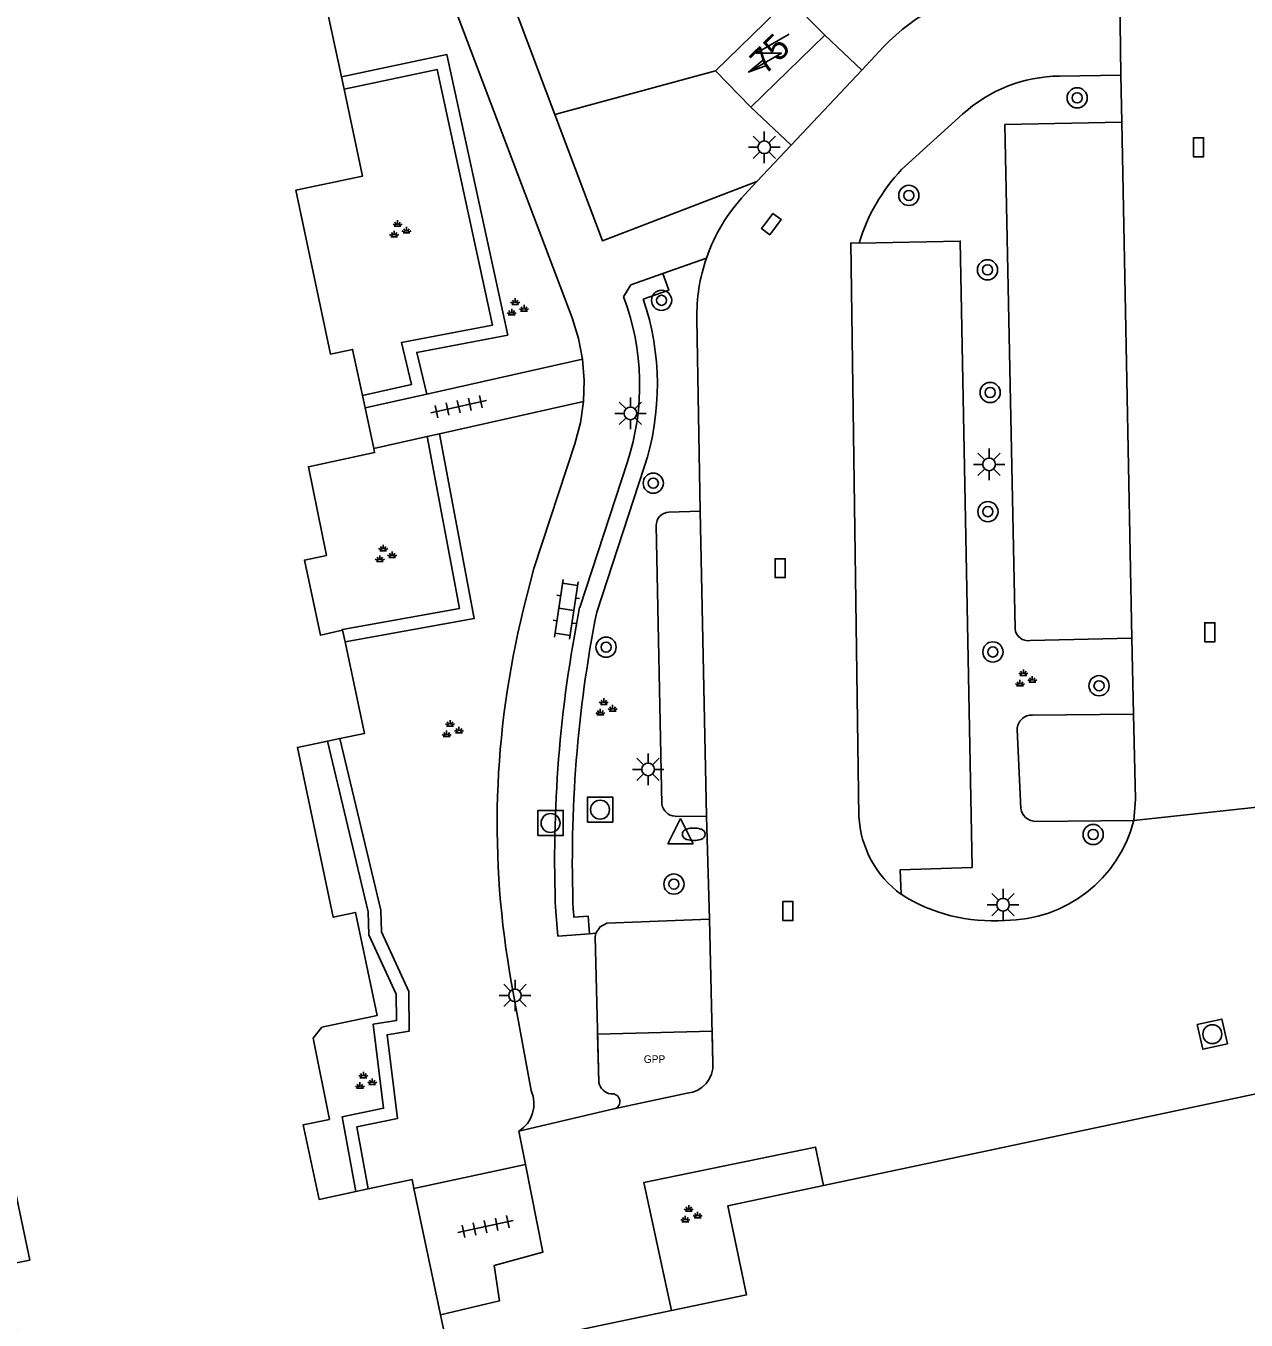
# Model space of a CAD drawing. Extents: x 132998 to 136004, y 396998 to 398512.
# Drawn here: x 133155.2 to 133203.5, y 397650.9 to 397702.1 of the extents above; entities that cross this region are included whole.
import ezdxf

# ---------------------------------------------------------------- set-up
doc = ezdxf.new("R2010")
doc.units = 0
for name, color, linetype in [('bp-grn-parkeervak', 7, 'Continuous'), ('gg-anno-huisnummerreeks BGT', 7, 'Continuous'), ('gg-bbg-hoofdgebouw', 7, 'Continuous'), ('gg-knt-verharding', 7, 'Continuous'), ('gg-knt-verharding nz', 7, 'Continuous'), ('gt-grn-groengrens', 7, 'Continuous'), ('gt-grn-weggrens', 7, 'Continuous'), ('gt-symb-boom', 7, 'Continuous'), ('gt-symb-brandkraan', 7, 'Continuous'), ('gt-symb-groenvak', 7, 'Continuous'), ('gt-symb-klinker verharding', 7, 'Continuous'), ('gt-symb-kolk', 7, 'Continuous'), ('gt-symb-lichtmast', 7, 'Continuous'), ('gt-symb-rioolschacht', 7, 'Continuous'), ('gt-symb-tegel verharding', 7, 'Continuous'), ('gt-symb-trafo symbool', 7, 'Continuous'), ('gt-symb-waterafsluiter', 7, 'Continuous'), ('kenmerkpunt gehandicapten parkeerplaats', 7, 'Continuous')]:
    doc.layers.add(name, color=color, linetype=linetype)

# ---------------------------------------------------------------- blocks, each defined once
blk = doc.blocks.new('gt0-HSP')
at = {"layer": 'gt-symb-trafo symbool'}
for points in [[(0.771, 0.746), (-0.529, -0.004), (0.471, -0.004), (-0.829, -0.754)], [(-0.217, -0.24), (-0.829, -0.754), (-0.077, -0.48)]]:
    blk.add_lwpolyline(points, dxfattribs=at)
blk = doc.blocks.new('gt0-KOLK')
at = {"layer": 'gt-symb-kolk'}
blk.add_lwpolyline([(0, 0), (0.375, 0), (0.375, 0.4), (-0.375, 0.4), (-0.375, 0), (0, 0)], dxfattribs=at)
blk = doc.blocks.new('gt0-BOOM')
at = {"layer": 'gt-symb-boom'}
for radius in [0.4, 0.2]:
    blk.add_circle((0, 0), radius, dxfattribs=at)
blk = doc.blocks.new('gt0-LMAST')
at = {"layer": 'gt-symb-lichtmast'}
for p, q in [((-0.005, 0.246), (-0.005, 0.621)), ((-0.182, 0.173), (-0.447, 0.438)), ((0.172, 0.173), (0.437, 0.438)), ((-0.255, -0.004), (-0.63, -0.004)), ((-0.182, -0.181), (-0.447, -0.446)), ((-0.005, -0.254), (-0.005, -0.629)), ((0.437, -0.446), (0.172, -0.181)), ((0.245, -0.004), (0.62, -0.004))]:
    blk.add_line(p, q, dxfattribs=at)
blk.add_circle((-0.005, -0.004), 0.25, dxfattribs=at)
blk = doc.blocks.new('gt0-GRVAK')
at = {"layer": 'gt-symb-groenvak'}
for p, q in [((-0.11, 0.189), (-0.228, 0.24)), ((-0.182, 0.153), (0.088, 0.153)), ((-0.091, 0.211), (-0.156, 0.322)), ((-0.047, 0.214), (-0.047, 0.393)), ((-0.004, 0.211), (0.061, 0.322)), ((0.015, 0.189), (0.133, 0.24)), ((0.262, -0.052), (0.197, 0.059)), ((0.305, -0.049), (0.305, 0.13)), ((0.349, -0.052), (0.414, 0.059)), ((-0.245, -0.228), (-0.363, -0.177)), ((-0.318, -0.264), (-0.047, -0.264)), ((-0.226, -0.206), (-0.291, -0.095)), ((-0.183, -0.203), (-0.183, -0.024)), ((-0.139, -0.206), (-0.074, -0.095)), ((-0.12, -0.228), (-0.002, -0.177)), ((0.243, -0.074), (0.125, -0.023)), ((0.17, -0.11), (0.441, -0.11)), ((0.368, -0.074), (0.486, -0.023))]:
    blk.add_line(p, q, dxfattribs=at)
blk = doc.blocks.new('gt0-TEG1')
at = {"layer": 'gt-symb-tegel verharding'}
for p, q in [((-1.125, 0), (1.125, 0)), ((-0.9, -0.25), (-0.9, 0.25)), ((-0.45, -0.25), (-0.45, 0.25)), ((0, -0.25), (0, 0.25)), ((0.45, -0.25), (0.45, 0.25)), ((0.9, -0.25), (0.9, 0.25))]:
    blk.add_line(p, q, dxfattribs=at)
blk = doc.blocks.new('gt0-KL1')
at = {"layer": 'gt-symb-klinker verharding'}
for p, q in [((-1.15, 0.3), (1.15, 0.3)), ((-1, -0.3), (-1, 0.3)), ((-0.5, 0.3), (-0.5, 0.45)), ((0, -0.3), (0, 0.3)), ((0.5, 0.3), (0.5, 0.45)), ((1, -0.3), (1, 0.3)), ((-1.15, -0.3), (1.15, -0.3)), ((-0.5, -0.45), (-0.5, -0.3)), ((0.5, -0.45), (0.5, -0.3))]:
    blk.add_line(p, q, dxfattribs=at)
blk = doc.blocks.new('gt0-WAFSL')
at = {"layer": 'gt-symb-waterafsluiter'}
for p, q in [((-0.5, -0.333), (0, 0.667)), ((0, 0.667), (0.5, -0.333)), ((0.5, -0.333), (-0.5, -0.333))]:
    blk.add_line(p, q, dxfattribs=at)
blk = doc.blocks.new('gt0-BR')
at = {"layer": 'gt-symb-brandkraan'}
for centre, radius, start, end in [((-0.244, 0), 0.206, 107.5669, 252.4331), ((0.599, -2.664), 3, 106.892, 107.5669), ((0, -0.691), 0.938, 73.108, 106.892), ((-0.599, -2.664), 3, 72.4331, 73.108), ((0.244, 0), 0.206, 287.567, 72.4331), ((0.599, 2.664), 3, 252.4331, 253.108), ((0, 0.691), 0.938, 253.108, 286.8921), ((-0.599, 2.664), 3, 286.8921, 287.567)]:
    blk.add_arc(centre, radius, start, end, dxfattribs=at)
blk = doc.blocks.new('gt0-RS')
at = {"layer": 'gt-symb-rioolschacht'}
blk.add_lwpolyline([(-0.5, -0.5), (0.5, -0.5), (0.5, 0.5), (-0.5, 0.5)], close=True, dxfattribs=at)
blk.add_circle((0, 0), 0.375, dxfattribs=at)

msp = doc.modelspace()

# ---------------------------------------------------------------- linework, layer by layer
at = {"layer": 'bp-grn-parkeervak'}
msp.add_line((133181.369, 397659.853), (133178.468, 397659.234), dxfattribs=at)
msp.add_lwpolyline([(133177.868, 397660.275), (133177.821, 397662.195), (133182.356, 397662.305), (133182.387, 397661.036)], dxfattribs=at)
for centre, radius, start, end in [((133181.258, 397660.978), 1.131, 275.6543, 2.9202), ((133178.44, 397660.408), 0.587, 193.0963, 260.5107), ((133178.399, 397659.53), 0.304, 283.1378, 100.591)]:
    msp.add_arc(centre, radius, start, end, dxfattribs=at)
at = {"layer": 'gg-bbg-hoofdgebouw'}
for p, q in [((133185.41, 397703.17), (133182.49, 397700.32)), ((133186.82, 397701.73), (133185.41, 397703.17)), ((133183.89, 397698.88), (133186.82, 397701.73)), ((133167.778, 397699.597), (133167.674, 397700.086)), ((133182.49, 397700.32), (133183.89, 397698.88)), ((133168.613, 397686.983), (133168.509, 397687.472)), ((133168.613, 397686.983), (133168.954, 397685.378)), ((133167.72, 397678.18), (133167.817, 397677.727)), ((133167.617, 397673.895), (133167.128, 397673.792)), ((133168.245, 397655.962), (133168.734, 397656.067)), ((133170.545, 397656.088), (133171.605, 397651.087))]:
    msp.add_line(p, q, dxfattribs=at)
for points in [[(133166.109, 397703.604), (133166.89, 397703.77), (133167.674, 397700.086)], [(133168.509, 397687.472), (133168.12, 397689.3), (133167.24, 397689.11), (133165.87, 397695.6), (133168.51, 397696.16), (133167.778, 397699.597)], [(133168.954, 397685.378), (133168.99, 397685.21), (133166.37, 397684.65), (133167.08, 397681.14), (133166.21, 397680.96), (133166.84, 397677.99), (133167.72, 397678.18)], [(133167.817, 397677.727), (133168.59, 397674.1), (133167.617, 397673.895)], [(133167.128, 397673.792), (133165.93, 397673.54), (133167.35, 397666.82), (133168.23, 397667.01), (133169.09, 397662.93), (133166.9, 397662.47), (133166.56, 397662.04), (133167.2, 397658.82), (133166.16, 397658.6), (133166.8, 397655.65), (133168.245, 397655.962)], [(133208.423, 397668.156), (133207.16, 397667.88), (133208.621, 397660.83), (133186.764, 397656.201)], [(133149.37, 397663.02), (133150.13, 397659.49), (133149.26, 397659.31), (133150.14, 397655.25), (133154.72, 397656.2), (133155.33, 397653.25), (133154.28, 397653.04), (133155.02, 397649.49), (133154.14, 397649.3), (133155.02, 397645.23), (133159.57, 397646.22), (133160.98, 397639.7), (133157.32, 397638.9), (133158.87, 397631.35), (133159.76, 397631.53), (133160.49, 397627.99)], [(133168.734, 397656.067), (133170.47, 397656.44), (133170.545, 397656.088)], [(133186.764, 397656.201), (133182.98, 397655.4), (133183.71, 397651.87), (133180.745, 397651.249)], [(133171.605, 397651.087), (133171.96, 397649.41), (133180.745, 397651.249)]]:
    msp.add_lwpolyline(points, dxfattribs=at)
at = {"layer": 'gg-knt-verharding'}
for p, q in [((133170.9, 397712.5), (133176.132, 397698.591)), ((133186.82, 397701.73), (133188.283, 397700.355)), ((133188.283, 397700.355), (133189.146, 397701.273)), ((133185.487, 397697.379), (133188.283, 397700.355)), ((133198.54, 397700.15), (133196.108, 397700.117)), ((133198.579, 397698.294), (133198.54, 397700.15)), ((133183.89, 397698.88), (133185.487, 397697.379)), ((133192.276, 397698.609), (133189.86, 397696.42)), ((133193.953, 397698.204), (133198.579, 397698.294)), ((133193.953, 397698.204), (133194.356, 397678.239)), ((133184.132, 397695.938), (133185.487, 397697.379)), ((133183.642, 397695.417), (133184.132, 397695.938)), ((133182.131, 397692.915), (133180.403, 397692.3)), ((133181.875, 397682.895), (133181.751, 397690.49)), ((133171.052, 397687.528), (133177.222, 397688.905)), ((133168.613, 397686.983), (133171.052, 397687.528)), ((133171.558, 397685.96), (133177.259, 397687.234)), ((133168.954, 397685.378), (133171.07, 397685.851)), ((133171.07, 397685.851), (133171.558, 397685.96)), ((133179.001, 397684.851), (133177.11, 397679.08)), ((133180.644, 397682.852), (133181.875, 397682.895)), ((133180.368, 397671.292), (133180.144, 397682.325)), ((133194.944, 397677.773), (133198.975, 397677.861)), ((133199.048, 397674.857), (133198.975, 397677.861)), ((133195.042, 397674.825), (133199.048, 397674.857)), ((133194.58, 397671.123), (133194.436, 397674.25)), ((133182.137, 397670.82), (133180.888, 397670.815)), ((133182.247, 397666.74), (133182.137, 397670.82)), ((133199.053, 397670.649), (133195.13, 397670.616)), ((133176.16, 397667.042), (133176.245, 397666.071)), ((133176.245, 397666.071), (133177.499, 397666.166)), ((133177.499, 397666.166), (133177.756, 397666.185)), ((133174.415, 397664.197), (133175.19, 397659.96)), ((133174.7, 397658.35), (133178.468, 397659.234)), ((133174.96, 397657.04), (133174.7, 397658.35)), ((133174.96, 397657.04), (133170.545, 397656.088))]:
    msp.add_line(p, q, dxfattribs=at)
for points in [[(133170.941, 397706.05), (133176.809, 397690.542), (133177.063, 397689.735), (133177.222, 397688.905)], [(133176.132, 397698.591), (133178.01, 397693.6), (133184.132, 397695.938)], [(133188.175, 397693.504), (133192.179, 397693.588), (133192.652, 397668.785), (133189.808, 397668.699), (133189.835, 397667.729)], [(133180.403, 397692.3), (133179.14, 397691.85), (133178.85, 397691.38)], [(133177.259, 397687.234), (133177.29, 397688.071), (133177.222, 397688.905)], [(133177.259, 397687.234), (133177.137, 397686.39), (133176.916, 397685.565), (133175.29, 397680.63), (133174.878, 397678.972)], [(133182.247, 397666.74), (133178.18, 397666.592), (133177.917, 397666.442), (133177.756, 397666.185)], [(133177.868, 397660.275), (133177.728, 397666.039), (133177.756, 397666.185)], [(133180.745, 397651.249), (133179.65, 397656.32), (133186.45, 397657.72), (133186.764, 397656.201)], [(133171.605, 397651.087), (133173.94, 397651.64), (133173.72, 397653.03), (133175.65, 397653.56), (133174.96, 397657.04)]]:
    msp.add_lwpolyline(points, dxfattribs=at)
for centre, radius, start, end in [((133194.576, 397696.168), 7.453, 95.9204, 136.7663), ((133196.186, 397694.295), 5.822, 90.7714, 132.1907), ((133195.175, 397691.404), 7.308, 136.6564, 163.301), ((133188.726, 397690.639), 6.977, 136.7804, 160.9627), ((133188.76, 397690.634), 7.011, 161.0117, 181.1766), ((133169.681, 397687.902), 9.806, 341.8745, 20.7753), ((133180.654, 397682.341), 0.511, 91.164, 181.848), ((133208.904, 397670.511), 35.062, 166.0358, 190.3744), ((133227.198, 397669.071), 51.079, 168.6993, 182.2762), ((133194.865, 397678.277), 0.51, 184.2585, 278.9466), ((133195.018, 397674.243), 0.582, 87.6818, 179.311), ((133180.916, 397671.368), 0.553, 187.8658, 267.0734), ((133195.167, 397671.208), 0.593, 188.2635, 266.3957), ((133193.955, 397671.963), 5.265, 269.9481, 345.5496), ((133193.441, 397673.394), 6.715, 237.521, 274.3475), ((133174.011, 397659.439), 1.289, 302.3196, 23.8254), ((133178.44, 397660.408), 0.587, 193.0963, 260.5107), ((133178.399, 397659.53), 0.304, 283.1378, 100.591)]:
    msp.add_arc(centre, radius, start, end, dxfattribs=at)
at = {"layer": 'gg-knt-verharding nz'}
for p, q in [((133198.579, 397698.294), (133198.975, 397677.861)), ((133182.137, 397670.82), (133181.875, 397682.895)), ((133182.387, 397661.036), (133182.247, 397666.74)), ((133178.468, 397659.234), (133181.369, 397659.853))]:
    msp.add_line(p, q, dxfattribs=at)
for points in [[(133188.17, 397670.811), (133187.849, 397693.516), (133188.175, 397693.504)], [(133199.048, 397674.857), (133199.116, 397671.495), (133199.053, 397670.649)]]:
    msp.add_lwpolyline(points, dxfattribs=at)
for centre, radius, start, end in [((133192.236, 397671.017), 4.072, 182.9011, 233.8577), ((133181.258, 397660.978), 1.131, 275.6543, 2.9202)]:
    msp.add_arc(centre, radius, start, end, dxfattribs=at)
at = {"layer": 'gt-grn-groengrens'}
for p, q in [((133176.132, 397698.591), (133182.49, 397700.32)), ((133179.666, 397684.633), (133177.788, 397678.902))]:
    msp.add_line(p, q, dxfattribs=at)
for points in [[(133171.052, 397687.528), (133170.657, 397689.177), (133174.259, 397689.865), (133171.843, 397700.973), (133167.674, 397700.086)], [(133167.778, 397699.597), (133171.46, 397700.38), (133173.661, 397690.26), (133170.049, 397689.57), (133170.447, 397687.905), (133168.509, 397687.472)], [(133180.403, 397692.3), (133180.638, 397691.64), (133179.629, 397691.281)], [(133167.72, 397678.18), (133167.712, 397678.216), (133172.347, 397679.046), (133171.07, 397685.851)], [(133171.558, 397685.96), (133172.931, 397678.643), (133167.817, 397677.727)], [(133167.128, 397673.792), (133168.732, 397667.032), (133168.762, 397666.12), (133169.84, 397663.772), (133169.85, 397662.732), (133168.929, 397662.588), (133169.346, 397659.258), (133167.708, 397658.922), (133168.245, 397655.962)], [(133167.617, 397673.895), (133169.23, 397667.099), (133169.258, 397666.237), (133170.339, 397663.884), (133170.354, 397662.305), (133169.485, 397662.169), (133169.9, 397658.861), (133168.287, 397658.53), (133168.734, 397656.067)], [(133177.499, 397666.166), (133177.446, 397666.864), (133176.882, 397666.821), (133176.859, 397667.086)]]:
    msp.add_lwpolyline(points, dxfattribs=at)
for centre, radius, start, end in [((133169.677, 397687.902), 10.51, 341.8806, 18.7572), ((133227.209, 397669.072), 50.39, 168.7504, 182.2586)]:
    msp.add_arc(centre, radius, start, end, dxfattribs=at)
at = {"layer": 'gt-grn-weggrens'}
for p, q in [((133198.5, 397703.74), (133198.54, 397700.15)), ((133199.053, 397670.649), (133207.636, 397671.584))]:
    msp.add_line(p, q, dxfattribs=at)

# ---------------------------------------------------------------- block references
at = {"layer": 'gt-symb-boom'}
for p in [(133196.812, 397699.254), (133190.147, 397695.392), (133193.261, 397692.445), (133180.354, 397691.24), (133193.364, 397687.591), (133180.025, 397684.003), (133193.276, 397682.875), (133178.155, 397677.509), (133193.474, 397677.321), (133197.677, 397675.985), (133197.443, 397670.094), (133180.842, 397668.134)]:
    msp.add_blockref('gt0-BOOM', p, dxfattribs=at)
at = {"layer": 'gt-symb-brandkraan'}
msp.add_blockref('gt0-BR', (133181.627, 397670.106), dxfattribs=at)
at = {"layer": 'gt-symb-groenvak'}
for p in [(133169.946, 397694.017), (133174.601, 397690.927), (133169.377, 397681.17), (133194.727, 397676.239), (133178.111, 397675.093), (133172.023, 397674.233), (133168.59, 397660.313), (133181.477, 397655.032)]:
    msp.add_blockref('gt0-GRVAK', p, dxfattribs=at)
at = {"layer": 'gt-symb-klinker verharding', "rotation": 81.43241009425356}
msp.add_blockref('gt0-KL1', (133176.582, 397679.006), dxfattribs=at)
at = {"layer": 'gt-symb-kolk'}
for p, rotation in [((133201.815, 397697.301), 90), ((133184.538, 397694.378), -126.5834211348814), ((133185.249, 397680.639), 90), ((133202.265, 397678.103), 90), ((133185.557, 397667.063), 90)]:
    msp.add_blockref('gt0-KOLK', p, dxfattribs=dict(at, rotation=rotation))
at = {"layer": 'gt-symb-lichtmast'}
for p in [(133184.424, 397697.302), (133179.127, 397686.769), (133193.33, 397684.75), (133179.826, 397672.675), (133193.879, 397667.321), (133174.554, 397663.728)]:
    msp.add_blockref('gt0-LMAST', p, dxfattribs=at)
at = {"layer": 'gt-symb-rioolschacht'}
for p in [(133177.917, 397671.079), (133175.957, 397670.55)]:
    msp.add_blockref('gt0-RS', p, dxfattribs=at)
at = {"layer": 'gt-symb-rioolschacht', "rotation": 102.29885516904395}
msp.add_blockref('gt0-RS', (133202.163, 397662.193), dxfattribs=at)
at = {"layer": 'gt-symb-tegel verharding'}
for p, rotation in [((133172.318, 397687.031), 12.590950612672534), ((133173.383, 397654.576), 12.174751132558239)]:
    msp.add_blockref('gt0-TEG1', p, dxfattribs=dict(at, rotation=rotation))
at = {"layer": 'gt-symb-trafo symbool'}
msp.add_blockref('gt0-HSP', (133184.631, 397701.031), dxfattribs=at)
at = {"layer": 'gt-symb-waterafsluiter', "rotation": -0.1718868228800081}
msp.add_blockref('gt0-WAFSL', (133181.107, 397670.06), dxfattribs=at)

# ---------------------------------------------------------------- texts
at = {"layer": 'gg-anno-huisnummerreeks BGT'}
msp.add_text('75', height=1, rotation=44.2, dxfattribs=at).set_placement((133184.447, 397700.125))
at = {"layer": 'kenmerkpunt gehandicapten parkeerplaats'}
msp.add_text('GPP', height=0.3, dxfattribs=at).set_placement((133179.65, 397661.055))

doc.saveas('drawing.dxf')
